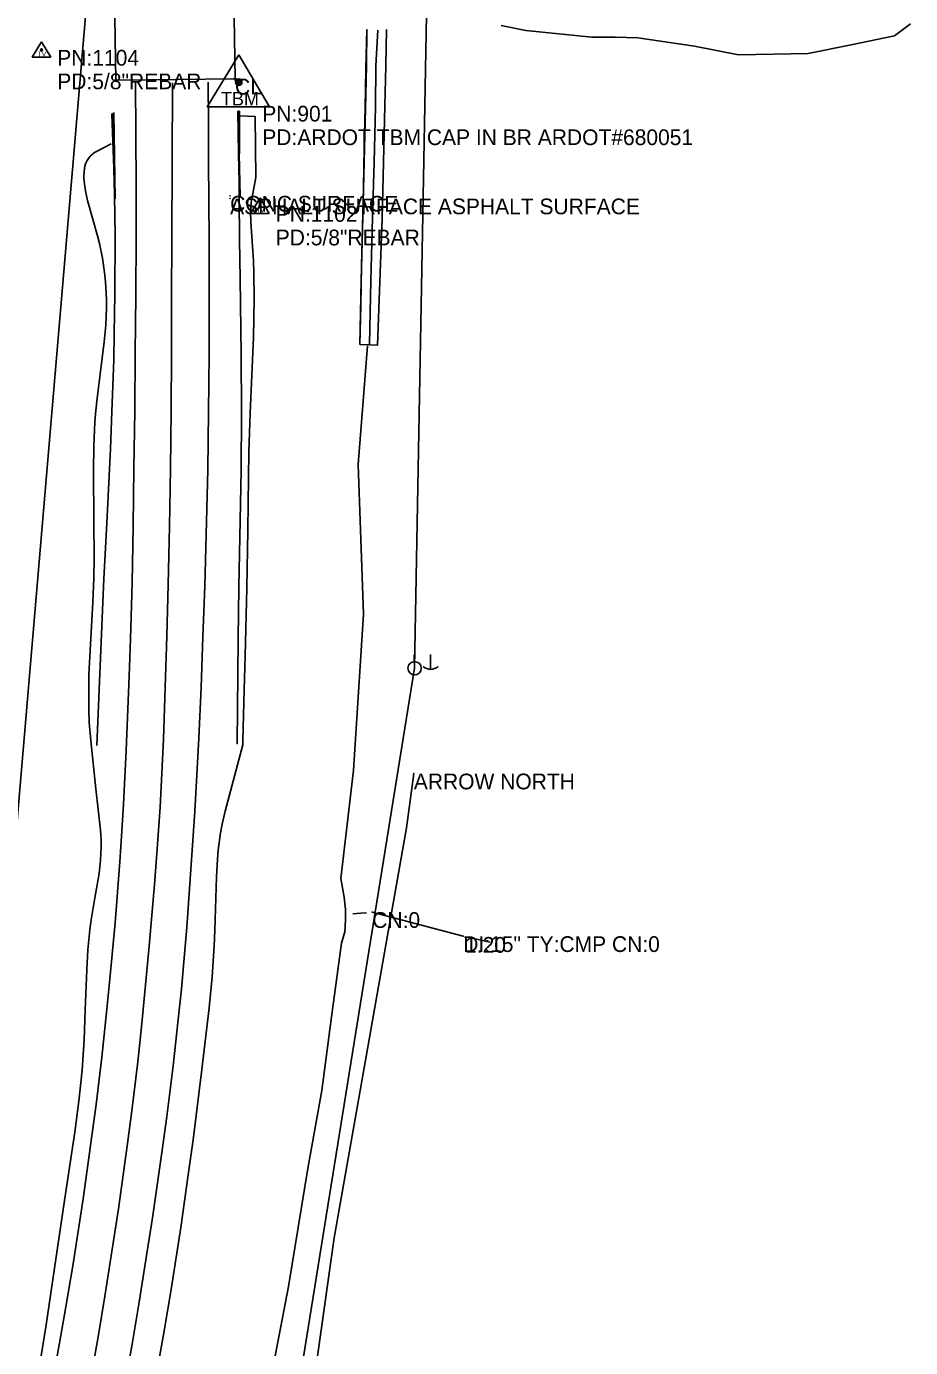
# Model space of a CAD drawing. Extents: x 1676038 to 1677961, y 226475 to 233854.
# Drawn here: x 1677413.5 to 1677694.8, y 228719 to 229139.3 of the extents above; entities that cross this region are included whole.
import ezdxf

# ---------------------------------------------------------------- set-up
doc = ezdxf.new("R2010")
doc.units = 0
for name, color, linetype in [('S_BASELINE', 7, 'Continuous'), ('S_BRIDGE', 7, 'Continuous'), ('S_BRIDGE_ANNOT', 7, 'Continuous'), ('S_CURB', 7, 'Continuous'), ('S_DITCHLINE', 7, 'Continuous'), ('S_DRG_PT_SYM', 7, 'Continuous'), ('S_DROP_INLET_ANNOT', 7, 'Continuous'), ('S_EDGE_CONCRETE', 7, 'Continuous'), ('S_EDGE_PAVEMENT', 7, 'Continuous'), ('S_ELECTRIC_UTILITIES', 7, 'Continuous'), ('S_FIBER_OPTIC_CABLE', 7, 'Continuous'), ('S_FIBER_OPTIC_CABLE_ANNOT', 7, 'Continuous'), ('S_GUARDRAIL', 7, 'Continuous'), ('S_MSC_PT_SYM', 7, 'Continuous'), ('S_PAVEMENT_CROWN', 7, 'Continuous'), ('S_PRIMARY_CTL', 7, 'Continuous'), ('S_PRIMARY_CTL_ANNOT', 7, 'Continuous'), ('S_RDW_PT_SYM', 7, 'Continuous'), ('S_SECONDARY_CTL', 7, 'Continuous'), ('S_SECONDARY_CTL_ANNOT', 7, 'Continuous'), ('S_SHOULDER', 7, 'Continuous'), ('S_SIDE_DRAIN', 7, 'Continuous'), ('S_SIDE_DRAIN_ANNOT', 7, 'Continuous'), ('S_STR_PT_SYM', 7, 'Continuous'), ('S_STREAM', 7, 'Continuous'), ('S_SURVEY_TEXT_ANNOT', 7, 'Continuous'), ('S_UTILITY_POLE', 7, 'Continuous'), ('S_UTL_PT_SYM', 7, 'Continuous')]:
    doc.layers.add(name, color=color, linetype=linetype)

msp = doc.modelspace()

# ---------------------------------------------------------------- linework, layer by layer
at = {"layer": 'S_BASELINE'}
msp.add_line((1677368.16, 228389.18), (1677436.38, 229190.98), dxfattribs=at)
at = {"layer": 'S_BRIDGE'}
for p, q in [((1677441.95, 229122.22), (1677441.12, 229176.97)), ((1677478.98, 229177.38), (1677479.86, 229122.68)), ((1677479.86, 229122.68), (1677441.95, 229122.22))]:
    msp.add_line(p, q, dxfattribs=at)
at = {"layer": 'S_CURB'}
msp.add_lwpolyline([(1677441.03, 229111.79), (1677441.26, 229098.22), (1677441.49, 229084.65), (1677441.72, 229084.58), (1677441.51, 229098.19), (1677441.3, 229111.8)], close=True, dxfattribs=at)
at = {"layer": 'S_DITCHLINE'}
for points in [[(1677522.63, 229038.26), (1677523.12, 229058.43), (1677523.6, 229078.59), (1677524.1, 229096.18), (1677524.6, 229113.77), (1677524.67, 229126.78), (1677525.27, 229138.2)], [(1677492.32, 228714.69), (1677496.91, 228738.44), (1677499.97, 228757.22), (1677503.03, 228775.99), (1677505.25, 228788.38), (1677507.46, 228800.77), (1677510.6, 228824.19), (1677513.73, 228847.61), (1677514.83, 228851.31), (1677515.02, 228854.93), (1677514.96, 228858.41), (1677514.63, 228862.29), (1677513.48, 228868.18), (1677515.51, 228885.41), (1677517.54, 228902.65), (1677519.12, 228927.5), (1677520.71, 228952.35), (1677519.88, 228976.18), (1677519.06, 229000), (1677520.55, 229018.83), (1677522.04, 229037.67)], [(1677517.33, 228856.94), (1677519.88, 228857.15), (1677521.64, 228857.29)], [(1677561.01, 228848), (1677553.85, 228849.54)]]:
    msp.add_lwpolyline(points, dxfattribs=at)
at = {"layer": 'S_DRG_PT_SYM'}
for points in [[(1677523.52, 228857.52), (1677523.52, 228857.57), (1677523.52, 228857.52), (1677523.47, 228857.52), (1677523.52, 228857.52), (1677523.52, 228857.47), (1677523.52, 228857.52), (1677523.57, 228857.52)], [(1677552.48, 228849.85), (1677552.48, 228849.9), (1677552.48, 228849.85), (1677552.43, 228849.85), (1677552.48, 228849.85), (1677552.48, 228849.8), (1677552.48, 228849.85), (1677552.53, 228849.85)], [(1677553.05, 228849.61), (1677553.05, 228849.66), (1677553.05, 228849.61), (1677553, 228849.61), (1677553.05, 228849.61), (1677553.05, 228849.56), (1677553.05, 228849.61), (1677553.1, 228849.61)]]:
    msp.add_lwpolyline(points, dxfattribs=at)
at = {"layer": 'S_EDGE_CONCRETE'}
for points in [[(1677519.57, 229038.13), (1677520.04, 229058.54), (1677520.52, 229078.95), (1677520.93, 229096.11), (1677521.34, 229113.27), (1677521.67, 229126.86), (1677521.82, 229138.35), (1677521.53, 229125.82), (1677521.25, 229113.29), (1677520.97, 229100.76), (1677520.69, 229088.24), (1677520.41, 229075.71), (1677520.13, 229063.18), (1677519.85, 229050.65)], [(1677480.74, 229112.39), (1677481.01, 229098.81), (1677481.28, 229085.22), (1677481.44, 229085.19), (1677481.19, 229098.78), (1677480.94, 229112.36)]]:
    msp.add_lwpolyline(points, close=True, dxfattribs=at)
msp.add_lwpolyline([(1677519.58, 229038.11), (1677522.68, 229037.98), (1677525.2, 229037.96), (1677525.95, 229058.08), (1677526.69, 229078.2), (1677527.11, 229096.11), (1677527.53, 229114.03), (1677527.87, 229126.76), (1677528.09, 229138.32)], dxfattribs=at)
at = {"layer": 'S_EDGE_PAVEMENT'}
for points in [[(1677421.11, 228704.51), (1677424.43, 228722.78), (1677426.02, 228731.93), (1677428.3, 228745.66), (1677431.48, 228766.31), (1677434.3, 228786.31), (1677435.61, 228796.33), (1677437.42, 228811.37), (1677438.99, 228825.61), (1677439.95, 228835.12), (1677441.69, 228854.14), (1677443.21, 228873.55), (1677443.86, 228883.26), (1677444.36, 228891.83), (1677445.2, 228908.97), (1677446.16, 228932.65), (1677446.57, 228944.49), (1677447.07, 228962.26), (1677447.45, 228980.47), (1677447.69, 228998.68), (1677447.94, 229016.89), (1677448.12, 229035.35), (1677448.29, 229053.8), (1677448.38, 229072.25), (1677448.38, 229088.73), (1677448.28, 229105.21), (1677448.18, 229121.69)], [(1677443.55, 228699.98), (1677447.09, 228720.05), (1677449.33, 228733.45), (1677451.44, 228746.87), (1677453.55, 228760.29), (1677456.69, 228781.76), (1677458.15, 228792.51), (1677460.17, 228808.65), (1677461.79, 228823.32), (1677462.77, 228833.1), (1677464.48, 228852.7), (1677465.41, 228864.99), (1677467.02, 228889.58), (1677468.3, 228912.92), (1677469.04, 228929.01), (1677469.62, 228945.1), (1677470.21, 228961.2), (1677470.9, 228985.89), (1677471.17, 228998.24), (1677471.46, 229016.76), (1677471.6, 229034.93), (1677471.6, 229053.1), (1677471.6, 229071.27), (1677471.53, 229083.86), (1677471.46, 229096.45), (1677471.39, 229109.03), (1677471.32, 229121.62)]]:
    msp.add_lwpolyline(points, dxfattribs=at)
at = {"layer": 'S_ELECTRIC_UTILITIES'}
for p, q in [((1677537.01, 228935.14), (1677541.67, 229188.26)), ((1677492.08, 228657.14), (1677537.01, 228935.14))]:
    msp.add_line(p, q, dxfattribs=at)
at = {"layer": 'S_FIBER_OPTIC_CABLE'}
for p, q in [((1677534.42, 228884.38), (1677536.75, 228901.6)), ((1677511.42, 228753.9), (1677534.42, 228884.38)), ((1677501.74, 228685.3), (1677511.42, 228753.9))]:
    msp.add_line(p, q, dxfattribs=at)
at = {"layer": 'S_GUARDRAIL'}
for p, q in [((1677481.21, 229085), (1677481.23, 229112.34)), ((1677441.28, 229094.28), (1677440.67, 229111.44)), ((1677441.49, 229085.7), (1677441.28, 229094.28)), ((1677441.66, 229072.83), (1677441.49, 229085.7)), ((1677481.3, 229071.32), (1677481.21, 229085)), ((1677441.63, 229054.13), (1677441.66, 229072.83)), ((1677481.45, 229059.15), (1677481.3, 229071.32)), ((1677481.81, 229034.81), (1677481.45, 229059.15)), ((1677441.44, 229041.66), (1677441.63, 229054.13)), ((1677441.24, 229033.35), (1677441.44, 229041.66)), ((1677440.69, 229016.73), (1677441.24, 229033.35)), ((1677481.93, 229016.55), (1677481.81, 229034.81)), ((1677440.18, 229004.92), (1677440.69, 229016.73)), ((1677481.78, 228998.05), (1677481.93, 229016.55)), ((1677439.02, 228981.3), (1677440.18, 229004.92)), ((1677481.09, 228961.05), (1677481.78, 228998.05)), ((1677438.13, 228963.59), (1677439.02, 228981.3)), ((1677437.33, 228945.95), (1677438.13, 228963.59)), ((1677480.86, 228944.41), (1677481.09, 228961.05)), ((1677435.91, 228910.66), (1677437.33, 228945.95)), ((1677480.54, 228911.14), (1677480.86, 228944.41))]:
    msp.add_line(p, q, dxfattribs=at)
at = {"layer": 'S_MSC_PT_SYM'}
for points in [[(1677478.28, 229084.57), (1677478.28, 229084.62), (1677478.28, 229084.57), (1677478.23, 229084.57), (1677478.28, 229084.57), (1677478.28, 229084.52), (1677478.28, 229084.57), (1677478.33, 229084.57)], [(1677478.29, 229085.42), (1677478.29, 229085.47), (1677478.29, 229085.42), (1677478.24, 229085.42), (1677478.29, 229085.42), (1677478.29, 229085.37), (1677478.29, 229085.42), (1677478.34, 229085.42)]]:
    msp.add_lwpolyline(points, dxfattribs=at)
at = {"layer": 'S_PAVEMENT_CROWN'}
msp.add_lwpolyline([(1677432.69, 228702.16), (1677436.31, 228722.44), (1677438.56, 228735.98), (1677440.65, 228749.55), (1677442.74, 228763.12), (1677445.66, 228783.88), (1677447.01, 228794.27), (1677448.87, 228809.88), (1677450.17, 228822.13), (1677452.49, 228846.67), (1677454.21, 228866.32), (1677454.98, 228876.16), (1677455.99, 228890.92), (1677457.05, 228912.61), (1677457.66, 228928.98), (1677458.11, 228945.37), (1677458.57, 228961.75), (1677458.95, 228980.23), (1677459.33, 228998.7), (1677459.56, 229017.18), (1677459.66, 229035.28), (1677459.68, 229053.38), (1677459.71, 229071.47), (1677459.84, 229096.45), (1677459.96, 229121.43)], dxfattribs=at)
at = {"layer": 'S_PRIMARY_CTL'}
for p, q in [((1677481.03, 229130.28), (1677470.99, 229113.77)), ((1677481.03, 229130.28), (1677490.85, 229113.77)), ((1677470.99, 229113.77), (1677490.85, 229113.77))]:
    msp.add_line(p, q, dxfattribs=at)
for radius in [1.04, 0.609, 0.344]:
    msp.add_circle((1677481.03, 229121.58), radius, dxfattribs=at)
at = {"layer": 'S_RDW_PT_SYM'}
for points in [[(1677481.23, 229112.34), (1677481.23, 229112.39), (1677481.23, 229112.34), (1677481.18, 229112.34), (1677481.23, 229112.34), (1677481.23, 229112.29), (1677481.23, 229112.34), (1677481.28, 229112.34)], [(1677440.67, 229111.44), (1677440.67, 229111.49), (1677440.67, 229111.44), (1677440.62, 229111.44), (1677440.67, 229111.44), (1677440.67, 229111.39), (1677440.67, 229111.44), (1677440.72, 229111.44)], [(1677441.66, 229072.83), (1677441.66, 229072.88), (1677441.66, 229072.83), (1677441.61, 229072.83), (1677441.66, 229072.83), (1677441.66, 229072.78), (1677441.66, 229072.83), (1677441.71, 229072.83)], [(1677481.3, 229071.32), (1677481.3, 229071.37), (1677481.3, 229071.32), (1677481.25, 229071.32), (1677481.3, 229071.32), (1677481.3, 229071.27), (1677481.3, 229071.32), (1677481.35, 229071.32)], [(1677440.69, 229016.73), (1677440.69, 229016.78), (1677440.69, 229016.73), (1677440.64, 229016.73), (1677440.69, 229016.73), (1677440.69, 229016.68), (1677440.69, 229016.73), (1677440.74, 229016.73)], [(1677481.93, 229016.55), (1677481.93, 229016.6), (1677481.93, 229016.55), (1677481.88, 229016.55), (1677481.93, 229016.55), (1677481.93, 229016.5), (1677481.93, 229016.55), (1677481.98, 229016.55)], [(1677438.13, 228963.59), (1677438.13, 228963.64), (1677438.13, 228963.59), (1677438.08, 228963.59), (1677438.13, 228963.59), (1677438.13, 228963.54), (1677438.13, 228963.59), (1677438.18, 228963.59)], [(1677481.09, 228961.05), (1677481.09, 228961.1), (1677481.09, 228961.05), (1677481.04, 228961.05), (1677481.09, 228961.05), (1677481.09, 228961), (1677481.09, 228961.05), (1677481.14, 228961.05)], [(1677435.91, 228910.66), (1677435.91, 228910.71), (1677435.91, 228910.66), (1677435.86, 228910.66), (1677435.91, 228910.66), (1677435.91, 228910.61), (1677435.91, 228910.66), (1677435.96, 228910.66)], [(1677480.54, 228911.14), (1677480.54, 228911.19), (1677480.54, 228911.14), (1677480.49, 228911.14), (1677480.54, 228911.14), (1677480.54, 228911.09), (1677480.54, 228911.14), (1677480.59, 228911.14)]]:
    msp.add_lwpolyline(points, dxfattribs=at)
at = {"layer": 'S_SECONDARY_CTL'}
for p, q in [((1677418.29, 229134.47), (1677415.28, 229129.52)), ((1677418.29, 229134.47), (1677421.24, 229129.52)), ((1677415.28, 229129.52), (1677421.24, 229129.52)), ((1677487.81, 229084.79), (1677484.8, 229079.84)), ((1677487.81, 229084.79), (1677490.75, 229079.84)), ((1677484.8, 229079.84), (1677490.75, 229079.84))]:
    msp.add_line(p, q, dxfattribs=at)
for centre, radius in [((1677418.29, 229131.86), 0.311), ((1677418.29, 229131.86), 0.183), ((1677418.29, 229131.86), 0.103), ((1677487.81, 229082.18), 0.311), ((1677487.81, 229082.18), 0.183), ((1677487.81, 229082.18), 0.103)]:
    msp.add_circle(centre, radius, dxfattribs=at)
at = {"layer": 'S_SHOULDER'}
for points in [[(1677455.02, 228711.19), (1677457.35, 228724.31), (1677459.53, 228737.45), (1677462.59, 228757.21), (1677464.98, 228773.94), (1677466.49, 228785.1), (1677469.34, 228807.44), (1677471.62, 228827.07), (1677472.53, 228836.91), (1677473.2, 228846.8), (1677473.42, 228851.77), (1677473.91, 228868.78), (1677474.26, 228874.41), (1677474.52, 228877.22), (1677475.26, 228882.78), (1677475.77, 228885.55), (1677476.72, 228889.65), (1677482.34, 228910.72), (1677482.37, 228912.13), (1677482.74, 228928.29), (1677483.05, 228939.06), (1677483.61, 228960.61), (1677483.9, 228979.19), (1677484.3, 229003.95), (1677484.68, 229016.32), (1677485.72, 229040.51), (1677485.97, 229052.63), (1677485.87, 229060.73), (1677485.72, 229064.79), (1677485.33, 229070.89), (1677484.86, 229077.21), (1677484.81, 229080.34), (1677485.03, 229083.45), (1677485.28, 229085), (1677486.51, 229091.31), (1677486.23, 229110.7), (1677481.28, 229110.91)], [(1677417.54, 228712.44), (1677419.8, 228726.27), (1677422.86, 228747.08), (1677425.93, 228767.89), (1677428.88, 228787.54), (1677430.18, 228797.38), (1677431.2, 228807.23), (1677431.57, 228812.17), (1677431.83, 228816.92), (1677432.17, 228826.45), (1677432.64, 228839.16), (1677433.05, 228845.52), (1677433.69, 228851.87), (1677434.11, 228855.04), (1677435.17, 228861.4), (1677436.58, 228869.86), (1677437.06, 228874.09), (1677437.29, 228878.32), (1677437.27, 228880.43), (1677437.04, 228883.6), (1677435.59, 228896.81), (1677434.14, 228910.02), (1677433.92, 228912.18), (1677433.47, 228917.9), (1677433.32, 228921.72), (1677433.29, 228929.34), (1677433.38, 228933.16), (1677433.72, 228940.81), (1677434.59, 228956.19), (1677434.91, 228963.94), (1677435.01, 228969.95), (1677434.96, 228981.99), (1677434.83, 228997.92), (1677434.94, 229005.74), (1677435.29, 229013.42), (1677435.59, 229017.18), (1677435.99, 229021.07), (1677436.97, 229028.74), (1677438.26, 229039.01), (1677438.71, 229044.26), (1677438.93, 229049.66), (1677438.92, 229052.43), (1677438.64, 229058.12), (1677438.35, 229061.06), (1677437.68, 229065.6), (1677436.71, 229070.31), (1677436.11, 229072.74), (1677434.73, 229077.57), (1677432.93, 229083.99), (1677432.24, 229087.06), (1677431.82, 229089.97), (1677431.74, 229091.35), (1677431.8, 229093.29), (1677432.09, 229094.89), (1677432.32, 229095.63), (1677432.78, 229096.67), (1677433.76, 229098.06), (1677435.12, 229099.22), (1677435.96, 229099.7), (1677440.46, 229101.97)]]:
    msp.add_lwpolyline(points, dxfattribs=at)
at = {"layer": 'S_SIDE_DRAIN'}
msp.add_line((1677552.48, 228849.85), (1677523.52, 228857.52), dxfattribs=at)
at = {"layer": 'S_STR_PT_SYM'}
for points in [[(1677441.95, 229122.22), (1677441.95, 229122.72), (1677441.95, 229122.22), (1677441.45, 229122.22), (1677441.95, 229122.22), (1677441.95, 229121.72), (1677441.95, 229122.22), (1677442.45, 229122.22)], [(1677479.86, 229122.68), (1677479.86, 229123.18), (1677479.86, 229122.68), (1677479.36, 229122.68), (1677479.86, 229122.68), (1677479.86, 229122.18), (1677479.86, 229122.68), (1677480.36, 229122.68)]]:
    msp.add_lwpolyline(points, dxfattribs=at)
at = {"layer": 'S_STREAM'}
msp.add_lwpolyline([(1677694.84, 229140.14), (1677689.74, 229136.3), (1677675.97, 229133.51), (1677662.2, 229130.73), (1677640.08, 229130.26), (1677626.04, 229133.07), (1677608, 229135.75), (1677600.84, 229135.91), (1677593.35, 229135.96), (1677572.37, 229138.06), (1677564.56, 229139.66)], dxfattribs=at)
at = {"layer": 'S_UTILITY_POLE'}
for p, q in [((1677536.88, 228937.28), (1677536.88, 228939.39)), ((1677542.05, 228939.47), (1677542.05, 228934.74))]:
    msp.add_line(p, q, dxfattribs=at)
msp.add_circle((1677537.01, 228935.14), 2.13, dxfattribs=at)
msp.add_arc((1677542.11, 228938.17), 3.41, 226.3972, 313.6028, dxfattribs=at)
at = {"layer": 'S_UTL_PT_SYM'}
for points in [[(1677537.01, 228935.14), (1677537.01, 228935.19), (1677537.01, 228935.14), (1677536.96, 228935.14), (1677537.01, 228935.14), (1677537.01, 228935.09), (1677537.01, 228935.14), (1677537.06, 228935.14)], [(1677536.75, 228901.6), (1677536.75, 228901.65), (1677536.75, 228901.6), (1677536.7, 228901.6), (1677536.75, 228901.6), (1677536.75, 228901.55), (1677536.75, 228901.6), (1677536.8, 228901.6)], [(1677534.42, 228884.38), (1677534.42, 228884.43), (1677534.42, 228884.38), (1677534.37, 228884.38), (1677534.42, 228884.38), (1677534.42, 228884.33), (1677534.42, 228884.38), (1677534.47, 228884.38)], [(1677511.42, 228753.9), (1677511.42, 228753.95), (1677511.42, 228753.9), (1677511.37, 228753.9), (1677511.42, 228753.9), (1677511.42, 228753.85), (1677511.42, 228753.9), (1677511.47, 228753.9)]]:
    msp.add_lwpolyline(points, dxfattribs=at)

# ---------------------------------------------------------------- texts
at = {"layer": 'S_BRIDGE_ANNOT'}
msp.add_text('CL', height=5, dxfattribs=at).set_placement((1677479.86, 229117.68))
at = {"layer": 'S_DROP_INLET_ANNOT'}
msp.add_text('1.20', height=5, dxfattribs=at).set_placement((1677553.05, 228844.61))
at = {"layer": 'S_FIBER_OPTIC_CABLE_ANNOT'}
msp.add_text('ARROW NORTH', height=5, dxfattribs=at).set_placement((1677536.75, 228896.6))
at = {"layer": 'S_PRIMARY_CTL'}
msp.add_text('TBM', height=4.287, rotation=360, dxfattribs=at).set_placement((1677475.37, 229114.19))
at = {"layer": 'S_PRIMARY_CTL_ANNOT'}
for s, p in [('PN:901', (1677488.53, 229109.08)), ('PD:ARDOT TBM CAP IN BR ARDOT#680051', (1677488.53, 229101.58))]:
    msp.add_text(s, height=5, dxfattribs=at).set_placement(p)
at = {"layer": 'S_SECONDARY_CTL'}
for p in [(1677417.09, 229129.85), (1677486.6, 229080.17)]:
    msp.add_text('TV', height=1.5, rotation=360, dxfattribs=at).set_placement(p)
at = {"layer": 'S_SECONDARY_CTL_ANNOT'}
for s, p in [('PN:1104', (1677423.29, 229126.86)), ('PD:5/8"REBAR', (1677423.29, 229119.36)), ('PN:1102', (1677492.81, 229077.18)), ('PD:5/8"REBAR', (1677492.81, 229069.68))]:
    msp.add_text(s, height=5, dxfattribs=at).set_placement(p)
at = {"layer": 'S_SIDE_DRAIN_ANNOT'}
for s, p in [('CN:0', (1677523.52, 228852.52)), ('DI:15" TY:CMP CN:0', (1677552.48, 228844.85))]:
    msp.add_text(s, height=5, dxfattribs=at).set_placement(p)
at = {"layer": 'S_SURVEY_TEXT_ANNOT'}
for s, p in [('ASPHALT SURFACE ASPHALT SURFACE', (1677478.28, 229079.57)), ('CONC SURFACE', (1677478.29, 229080.42))]:
    msp.add_text(s, height=5, dxfattribs=at).set_placement(p)

doc.saveas('drawing.dxf')
